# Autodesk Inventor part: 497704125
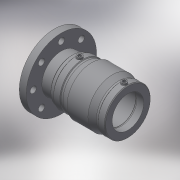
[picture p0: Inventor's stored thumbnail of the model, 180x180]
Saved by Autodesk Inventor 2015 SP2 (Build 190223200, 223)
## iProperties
Created: 2017-06
Part Number: 497704125
Material: Generic
Description: PLASSON PE CAST IRON SPIGOT COUPLER TRANSITION 225-200
Document SubType Name: Modeling
Designer: KIM
Mass: 55.0731 g
Surface Area: 148.067 cm^2
Volume: 55.0731 cm^3
Density: 1 g/cm^3
Appearance: Default
Author: KIM
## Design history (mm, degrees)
derived "497704.ipt"
feature "Solid1::497704.ipt"
tag "TaggingFeature1"
body "Solid1"
other parameters: "d13" = 173, "d14" = 17.6296, "d15" = 85, "d16" = 85, "d17" = 118.75, "d18" = 125, "d19" = 3.52592, "d20" = 168 deg, "d22" = 149.46, "d23" = 159, "d24" = 144.9762, "d25" = 135 deg, "d26" = 69.2, "d27" = 135 deg, "d29" = 87, "d35" = 15, "d39" = 5 deg, "d45" = 4, "d46" = 14, "d47" = 0, "d50" = 3, "d51" = 0, "d52" = 24.65, "d53" = 6.1625, "d55" = 0.1, "d56" = 141.51, "d58" = 62, "d60" = 98, "d62" = 4.77, "d65" = 3.18, "d68" = 159, "d70" = 22, "d71" = 7.33333, "d72" = 127.359, "d73" = 13.2, "d74" = 18, "d77" = 0, "d79" = 360 deg, "d_" = 125, "L_" = 235, "L_1" = 85, "D_1" = 159, "A_" = 87, "d_2" = 12, "L_2" = 62, "H_" = 109, "d_1" = 98, "t_" = 22, "S_" = 18
